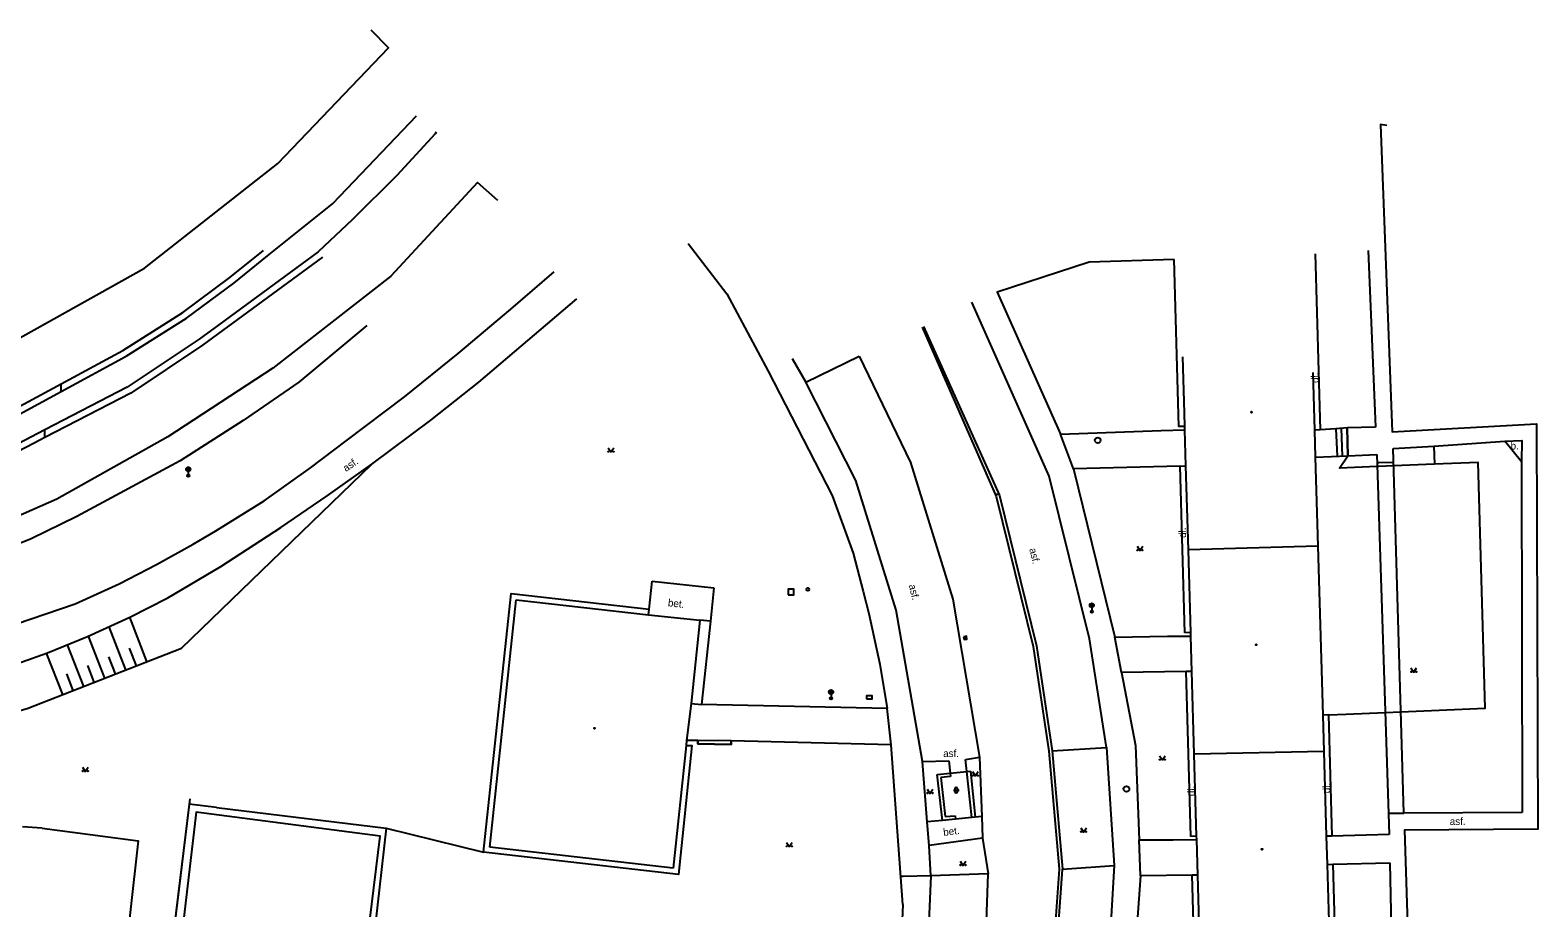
# Model space of a CAD drawing. Extents: x -602419 to -601554, y -1162937 to -1162362.
# Drawn here: x -601838.6 to -601705.2, y -1162455.9 to -1162378.3 of the extents above; entities that cross this region are included whole.
import ezdxf

# ---------------------------------------------------------------- set-up
doc = ezdxf.new("R2010")
doc.units = 0
doc.layers.add('Podklad', color=7, linetype='Continuous')

msp = doc.modelspace()

# ---------------------------------------------------------------- linework, layer by layer
at = {"layer": 'Podklad'}
for p, q in [((-601824.7525, -1162417.25), (-601824.4875, -1162416.985)), ((-601824.7525, -1162416.985), (-601824.4875, -1162417.25)), ((-601824.62, -1162417.305), (-601824.62, -1162417.68)), ((-601744.8325, -1162429.28), (-601744.5675, -1162429.015)), ((-601744.8325, -1162429.015), (-601744.5675, -1162429.28)), ((-601744.7, -1162429.335), (-601744.7, -1162429.71)), ((-601755.9198, -1162431.9066), (-601755.8802, -1162432.1534)), ((-601767.8925, -1162436.95), (-601767.6275, -1162436.685)), ((-601767.8925, -1162436.685), (-601767.6275, -1162436.95)), ((-601767.76, -1162437.005), (-601767.76, -1162437.38)), ((-601756.943, -1162445.488), (-601756.443, -1162445.488)), ((-601756.818, -1162445.363), (-601756.818, -1162445.613)), ((-601756.568, -1162445.363), (-601756.568, -1162445.613))]:
    msp.add_line(p, q, dxfattribs=at)
for points in [[(-601865.9699, -1162413.44), (-601868.073, -1162416.225), (-601860.681, -1162414.433), (-601851.512, -1162411.249), (-601843.288, -1162407.585), (-601828.487, -1162399.344), (-601816.71, -1162390.08), (-601806.918, -1162379.855), (-601808.45, -1162378.3)], [(-601898.07, -1162425.19), (-601894.4699, -1162425.26), (-601889.76, -1162425.42), (-601879.08, -1162424.2199), (-601865.29, -1162421.68), (-601852.18, -1162417.85), (-601841.55, -1162413.2199), (-601839.55, -1162412.24), (-601835.86, -1162410.24), (-601830.12, -1162407.13), (-601824.77, -1162403.76), (-601820.58, -1162400.6599), (-601817.6, -1162398.25), (-601811.85, -1162393.6599), (-601811.18, -1162392.96), (-601804.44, -1162385.87)], [(-601802.7, -1162387.31), (-601802.79, -1162387.45), (-601806.1599, -1162391.14), (-601810.09, -1162395.04), (-601813.14, -1162397.9), (-601821.9099, -1162404.34), (-601823.6599, -1162405.63), (-601830.02, -1162409.87), (-601837.31, -1162413.64), (-601838.54, -1162414.28), (-601842.26, -1162416.2199), (-601851.73, -1162420.1), (-601864.69, -1162423.83), (-601878.79, -1162426.46), (-601889.23, -1162427.52), (-601894.11, -1162427.5), (-601898.33, -1162427.48)], [(-601718.62, -1162386.7199), (-601719.1599, -1162386.65), (-601718.15, -1162413.82), (-601705.36, -1162413.11), (-601705.25, -1162448.94), (-601717.05, -1162449.02), (-601716.04, -1162480.32), (-601716.4099, -1162484.2199), (-601717.94, -1162489.4099), (-601746.45, -1162544.74), (-601749.56, -1162549.13)], [(-601797.24, -1162393.36), (-601799.042, -1162391.753), (-601806.692, -1162400.048), (-601817.129, -1162408.181), (-601826.438, -1162414.264), (-601836.254, -1162419.771), (-601849.065, -1162425.393), (-601857.06, -1162427.881), (-601870.816, -1162431.084), (-601881.829, -1162432.559), (-601893.35, -1162433.204), (-601893.374, -1162435.473)], [(-601898, -1162424.6), (-601894.45, -1162424.6599), (-601889.78, -1162424.82), (-601879.17, -1162423.62), (-601865.43, -1162421.1), (-601852.38, -1162417.28), (-601841.8, -1162412.68), (-601839.83, -1162411.71), (-601835.86, -1162409.56), (-601830.42, -1162406.61), (-601825.11, -1162403.27), (-601820.95, -1162400.18), (-601817.9699, -1162397.78)], [(-601780.39, -1162397.1599), (-601776.99, -1162401.62), (-601773.33, -1162408.45), (-601767.68, -1162419.45)], [(-601724.96, -1162398.06), (-601724.5, -1162413.64)], [(-601720.26, -1162397.79), (-601719.62, -1162413.39)], [(-601812.75, -1162398.36), (-601823.35, -1162406.15), (-601829.71, -1162410.39), (-601837.31, -1162414.32), (-601838.26, -1162414.81), (-601842.01, -1162416.77), (-601851.54, -1162420.6599), (-601864.55, -1162424.4099), (-601878.7, -1162427.06), (-601889.2, -1162428.12), (-601894.11, -1162428.1), (-601898.4, -1162428.09)], [(-601737.4099, -1162398.58), (-601744.95, -1162398.8), (-601753.06, -1162401.4699), (-601747.4699, -1162414.01), (-601738.57, -1162413.69), (-601736.4699, -1162413.64)], [(-601736.48, -1162413.34), (-601736.99, -1162413.35), (-601737.4099, -1162398.58)], [(-601834.62, -1162429.02), (-601830.7199, -1162427.24), (-601827.43, -1162425.54), (-601824.2, -1162423.73), (-601822.17, -1162422.57), (-601817.9099, -1162419.9), (-601813.81, -1162416.99), (-601810.64, -1162414.6), (-601805.48, -1162410.71), (-601800.75, -1162406.88), (-601796.1, -1162402.96), (-601792.25, -1162399.6599)], [(-601798.92, -1162409.4099), (-601790.24, -1162402.04)], [(-601743.4, -1162441.71), (-601744.9099, -1162432.12), (-601748.4699, -1162417.7199), (-601755.3, -1162402.35)], [(-601808.82, -1162404.4), (-601814.83, -1162409.42), (-601819.76, -1162412.82), (-601825.35, -1162416.38), (-601834.49, -1162421.29), (-601838.52, -1162423.27), (-601845.5, -1162426.1)], [(-601759.7, -1162404.55), (-601753.15, -1162419.52), (-601749.88, -1162432.78), (-601748.51, -1162442.04), (-601747.59, -1162452.46), (-601748.62, -1162466.9), (-601751, -1162479.06), (-601751.81, -1162481.88), (-601753.73, -1162488.54)], [(-601759.6, -1162404.5), (-601752.86, -1162419.44), (-601749.59, -1162432.7199), (-601748.21, -1162442.01)], [(-601771.2, -1162407.34), (-601770, -1162409.43)], [(-601770, -1162409.43), (-601765.28, -1162407.12)], [(-601765.28, -1162407.12), (-601760.74, -1162416.52), (-601756.98, -1162428.6), (-601754.64, -1162442.58)], [(-601736.51, -1162412.13), (-601736.65, -1162407.19)], [(-601725.15, -1162408.56), (-601725, -1162413.6599)], [(-601835.86, -1162410.24), (-601835.86, -1162409.56)], [(-601808.38, -1162416.6599), (-601803.17, -1162412.77), (-601798.92, -1162409.4099)], [(-601765.57, -1162418.11), (-601770, -1162409.43)], [(-601736.48, -1162413.34), (-601736.51, -1162412.13)], [(-601837.31, -1162414.32), (-601837.31, -1162413.64)], [(-601746.32, -1162417.07), (-601747.4699, -1162414.01)], [(-601736.4699, -1162413.64), (-601736.48, -1162413.34)], [(-601736.38, -1162416.81), (-601736.4699, -1162413.64)], [(-601724.5, -1162413.64), (-601725, -1162413.6599)], [(-601725, -1162413.6599), (-601724.94, -1162416.06)], [(-601723.12, -1162413.55), (-601724.5, -1162413.64)], [(-601722.12, -1162413.45), (-601723.12, -1162413.55)], [(-601723.12, -1162413.55), (-601723.01, -1162415.9699)], [(-601714.38, -1162416.67), (-601718.004, -1162416.8242), (-601719.31, -1162416.8799), (-601719.4651, -1162416.8868), (-601722.79, -1162417.0299), (-601722.06, -1162415.93), (-601722.12, -1162413.45)], [(-601722.53, -1162415.95), (-601722.62, -1162413.5)], [(-601719.62, -1162413.39), (-601722.12, -1162413.45)], [(-601722.12, -1162413.45), (-601722.06, -1162415.93)], [(-601787.48, -1162415.215), (-601787.23, -1162415.59), (-601786.98, -1162415.215)], [(-601718.05, -1162415.28), (-601714.44, -1162415.07)], [(-601717.09, -1162447.52), (-601718.05, -1162415.28)], [(-601714.44, -1162415.07), (-601708.1599, -1162414.63)], [(-601714.44, -1162415.07), (-601714.38, -1162416.67)], [(-601708.1599, -1162414.63), (-601706.68, -1162414.58), (-601706.7, -1162416.45)], [(-601706.7, -1162416.45), (-601708.1599, -1162414.63)], [(-601893.37, -1162444.62), (-601884.84, -1162446.24), (-601877.27, -1162446.73), (-601857.63, -1162443.6), (-601838.87, -1162438.26), (-601825.21, -1162432.93), (-601808.38, -1162416.6599)], [(-601848.2199, -1162436.84), (-601842, -1162435.09), (-601837.07, -1162433.34), (-601833.53, -1162431.9), (-601829.8, -1162430.19), (-601826.44, -1162428.48), (-601821.73, -1162425.7), (-601816.42, -1162422.27), (-601812.33, -1162419.46), (-601808.38, -1162416.6599)], [(-601736.88, -1162416.83), (-601746.32, -1162417.07), (-601742.68, -1162431.95), (-601738.02, -1162431.87), (-601735.94, -1162431.86)], [(-601736.88, -1162416.83), (-601736.38, -1162416.81)], [(-601736.46, -1162431.57), (-601736.88, -1162416.83)], [(-601736.1599, -1162424.24), (-601736.38, -1162416.81)], [(-601724.94, -1162416.06), (-601722.06, -1162415.93)], [(-601724.94, -1162416.06), (-601724.7, -1162423.9099)], [(-601723.78, -1162438.84), (-601722.2, -1162438.76), (-601718.7599, -1162438.6171), (-601717.3568, -1162438.5588), (-601709.92, -1162438.2499), (-601710.52, -1162416.51), (-601714.38, -1162416.67)], [(-601722.06, -1162415.93), (-601719.5, -1162415.81)], [(-601719.5, -1162415.81), (-601718.4099, -1162449.4)], [(-601718.013, -1162416.5223), (-601719.32, -1162416.5599), (-601719.4755, -1162416.5644)], [(-601706.7, -1162416.45), (-601706.65, -1162447.45)], [(-601762.02, -1162429.58), (-601765.57, -1162418.11)], [(-601767.68, -1162419.45), (-601765.82, -1162424.53), (-601764.93, -1162427.92), (-601764.42, -1162429.87), (-601763.45, -1162434.35), (-601762.8, -1162438.26)], [(-601752.9016, -1162419.3479), (-601753.225, -1162419.348)], [(-601740.7, -1162423.925), (-601740.45, -1162424.3), (-601740.2, -1162423.925)], [(-601724.7, -1162423.9099), (-601736.1599, -1162424.24)], [(-601735.95, -1162431.56), (-601736.1599, -1162424.24)], [(-601724.7, -1162423.9099), (-601724.28, -1162438.85)], [(-601783.86, -1162429.48), (-601783.59, -1162427.01)], [(-601783.59, -1162427.01), (-601778.13, -1162427.61)], [(-601780.58, -1162441.54), (-601780.09, -1162441.54), (-601781.27, -1162452.93), (-601798.5, -1162450.98), (-601796.06, -1162428.1), (-601783.86, -1162429.48)], [(-601797.95, -1162450.54), (-601795.62, -1162428.6599)], [(-601795.62, -1162428.6599), (-601783.92, -1162429.98)], [(-601778.13, -1162427.61), (-601778.44, -1162430.56)], [(-601848.83, -1162433.85), (-601834.62, -1162429.02)], [(-601828.27, -1162434.12), (-601829.8, -1162430.19)], [(-601783.92, -1162429.98), (-601783.86, -1162429.48)], [(-601783.92, -1162429.98), (-601779.36, -1162430.4699)], [(-601759.69, -1162442.94), (-601762.02, -1162429.58)], [(-601830.13, -1162434.85), (-601831.62, -1162431.05)], [(-601779.36, -1162430.4699), (-601780.15, -1162437.84)], [(-601778.44, -1162430.56), (-601779.36, -1162430.4699)], [(-601778.44, -1162430.56), (-601779.2199, -1162437.9)], [(-601833.86, -1162436.31), (-601835.29, -1162432.64)], [(-601832, -1162435.58), (-601833.45, -1162431.86)], [(-601742.08, -1162435.09), (-601742.68, -1162431.95)], [(-601735.95, -1162431.56), (-601736.46, -1162431.57)], [(-601735.94, -1162431.86), (-601735.95, -1162431.56)], [(-601735.86, -1162434.99), (-601735.94, -1162431.86)], [(-601835.7199, -1162437.03), (-601837.15, -1162433.37)], [(-601831.07, -1162435.21), (-601831.65, -1162433.71)], [(-601829.2, -1162434.49), (-601829.81, -1162432.94)], [(-601834.79, -1162436.67), (-601835.36, -1162435.21)], [(-601832.93, -1162435.94), (-601833.5, -1162434.4699)], [(-601736.36, -1162435), (-601742.08, -1162435.09), (-601740.85, -1162441.53), (-601740.51, -1162449.88), (-601737.52, -1162449.89), (-601735.42, -1162449.86)], [(-601735.86, -1162434.99), (-601736.36, -1162435)], [(-601735.94, -1162449.58), (-601736.36, -1162435)], [(-601735.64, -1162442.31), (-601735.86, -1162434.99)], [(-601716.4699, -1162434.675), (-601716.2199, -1162435.05), (-601715.9699, -1162434.675)], [(-601780.15, -1162437.84), (-601780.54, -1162441.09)], [(-601780.15, -1162437.84), (-601779.2199, -1162437.9)], [(-601762.8, -1162438.26), (-601779.2199, -1162437.9)], [(-601762.44, -1162441.48), (-601762.8, -1162438.26)], [(-601723.78, -1162438.84), (-601724.28, -1162438.85)], [(-601724.28, -1162438.85), (-601724.18, -1162442.08)], [(-601723.78, -1162438.84), (-601723.4699, -1162449.54)], [(-601780.58, -1162441.54), (-601781.7199, -1162452.37)], [(-601780.54, -1162441.09), (-601780.58, -1162441.54)], [(-601762.44, -1162441.48), (-601776.6, -1162441.14), (-601779.54, -1162441.1), (-601780.54, -1162441.09)], [(-601779.54, -1162441.1), (-601779.54, -1162441.3999), (-601776.6, -1162441.4399), (-601776.6, -1162441.14)], [(-601776.6, -1162441.14), (-601776.6, -1162441.44), (-601779.54, -1162441.4), (-601779.54, -1162441.1)], [(-601761.4099, -1162455.6), (-601762.44, -1162441.48)], [(-601748.21, -1162442.01), (-601743.4, -1162441.71)], [(-601748.21, -1162442.01), (-601747.29, -1162452.46)], [(-601743.4, -1162441.71), (-601742.71, -1162452.15)], [(-601724.18, -1162442.08), (-601735.64, -1162442.31)], [(-601724.18, -1162442.08), (-601723.9699, -1162449.56)], [(-601833.98, -1162443.455), (-601833.73, -1162443.83), (-601833.48, -1162443.455)], [(-601759.69, -1162442.94), (-601757.34, -1162442.9)], [(-601759.26, -1162448.3), (-601759.69, -1162442.94)], [(-601757.34, -1162442.9), (-601757.24, -1162443.99)], [(-601755.86, -1162442.78), (-601754.64, -1162442.58)], [(-601755.75, -1162443.85), (-601755.86, -1162442.78)], [(-601754.64, -1162442.58), (-601754.44, -1162447.81)], [(-601738.71, -1162442.445), (-601738.46, -1162442.82), (-601738.21, -1162442.445)], [(-601735.43, -1162449.56), (-601735.64, -1162442.31)], [(-601758.39, -1162444.1), (-601757.24, -1162443.99)], [(-601757.92, -1162448.1599), (-601758.39, -1162444.1)], [(-601757.21, -1162444.29), (-601758.06, -1162444.37)], [(-601758.06, -1162444.37), (-601757.6599, -1162447.83)], [(-601757.24, -1162443.99), (-601755.75, -1162443.85)], [(-601757.24, -1162443.99), (-601757.21, -1162444.29)], [(-601755.75, -1162443.85), (-601755.44, -1162443.82)], [(-601755.31, -1162447.9), (-601755.75, -1162443.85)], [(-601755.44, -1162443.82), (-601755.01, -1162447.87)], [(-601755.26, -1162443.8449), (-601755.01, -1162444.2199), (-601754.76, -1162443.8449)], [(-601759.27, -1162445.395), (-601759.02, -1162445.77), (-601758.77, -1162445.395)], [(-601769.18, -1162491.29), (-601808.78, -1162486.76), (-601826.77, -1162484.63), (-601826.06, -1162478.28), (-601826.06, -1162478.24), (-601826, -1162477.71), (-601813.39, -1162479.15), (-601811.31, -1162479.39), (-601807.65, -1162449.55), (-601823.91, -1162447.44), (-601827.44, -1162477.36), (-601827.52, -1162478.12), (-601828.2, -1162484.27), (-601829.06, -1162484.16), (-601831.79, -1162483.87), (-601832.64, -1162483.78)], [(-601822.13, -1162447.02), (-601824.55, -1162446.72), (-601828.37, -1162478.04), (-601827.52, -1162478.12), (-601826.06, -1162478.28)], [(-601824.49, -1162446.24), (-601828.24, -1162476.98)], [(-601822.13, -1162447.02), (-601807.12, -1162448.84), (-601810.61, -1162479.89), (-601826.06, -1162478.28)], [(-601718.4706, -1162447.5306), (-601717.09, -1162447.52)], [(-601706.65, -1162447.45), (-601717.09, -1162447.52)], [(-601837.55, -1162448.85), (-601839.27, -1162448.74)], [(-601837.55, -1162448.85), (-601829.04, -1162449.96), (-601832.49, -1162480.85)], [(-601807.12, -1162448.8399), (-601798.5, -1162450.98)], [(-601757.92, -1162448.1599), (-601759.26, -1162448.3)], [(-601759.09, -1162450.37), (-601759.26, -1162448.3)], [(-601756.76, -1162448.04), (-601757.92, -1162448.1599)], [(-601757.6599, -1162447.83), (-601756.79, -1162447.75)], [(-601756.79, -1162447.75), (-601756.76, -1162448.04)], [(-601755.31, -1162447.9), (-601756.76, -1162448.04)], [(-601755.01, -1162447.87), (-601755.31, -1162447.9)], [(-601754.44, -1162447.81), (-601755.01, -1162447.87)], [(-601754.44, -1162447.81), (-601754.37, -1162449.74)], [(-601745.68, -1162448.815), (-601745.43, -1162449.19), (-601745.18, -1162448.815)], [(-601771.71, -1162450.105), (-601771.46, -1162450.48), (-601771.21, -1162450.105)], [(-601754.37, -1162449.74), (-601759.09, -1162450.37)], [(-601754.37, -1162449.74), (-601753.88, -1162452.88)], [(-601740.4, -1162453.07), (-601740.51, -1162449.88)], [(-601735.43, -1162449.56), (-601735.94, -1162449.58)], [(-601735.42, -1162449.86), (-601735.43, -1162449.56)], [(-601735.33, -1162452.99), (-601735.42, -1162449.86)], [(-601723.4699, -1162449.54), (-601723.9699, -1162449.56)], [(-601723.9699, -1162449.56), (-601723.89, -1162452.06)], [(-601718.4099, -1162449.4), (-601723.4699, -1162449.54)], [(-601781.7199, -1162452.37), (-601797.95, -1162450.54)], [(-601758.94, -1162453.05), (-601759.09, -1162450.37)], [(-601756.35, -1162451.765), (-601756.1, -1162452.14), (-601755.85, -1162451.765)], [(-601750.71, -1162479.13), (-601748.32, -1162466.94), (-601747.29, -1162452.46)], [(-601747.29, -1162452.46), (-601742.71, -1162452.15)], [(-601742.71, -1162452.15), (-601743.65, -1162467.7)], [(-601723.89, -1162452.06), (-601723.39, -1162452.04)], [(-601723.89, -1162452.06), (-601723.6599, -1162460.06)], [(-601723.39, -1162452.04), (-601718.35, -1162451.9)], [(-601723.39, -1162452.04), (-601722.94, -1162467.8)], [(-601718.35, -1162451.9), (-601718.01, -1162467.6599)], [(-601758.94, -1162453.05), (-601759.31, -1162461.84), (-601760.52, -1162469.84), (-601761.77, -1162476.23)], [(-601758.94, -1162453.05), (-601761.39, -1162453.1199), (-601761.5904, -1162453.1256)], [(-601753.88, -1162452.88), (-601758.94, -1162453.05)], [(-601756.88, -1162477.28), (-601755.39, -1162470.09), (-601754.18, -1162462.14), (-601753.88, -1162452.88)], [(-601735.84, -1162453.01), (-601740.4, -1162453.07), (-601741.48, -1162468.11), (-601736.96, -1162467.96), (-601734.9, -1162467.85)], [(-601735.33, -1162452.99), (-601735.84, -1162453.01)], [(-601735.4099, -1162467.56), (-601735.84, -1162453.01)], [(-601735.12, -1162460.39), (-601735.33, -1162452.99)], [(-601761.4099, -1162455.6), (-601761.64, -1162461.06), (-601762.9699, -1162469.44)]]:
    msp.add_lwpolyline(points, dxfattribs=at)
for points in [[(-601771.56, -1162428.23), (-601771.06, -1162428.23), (-601771.06, -1162427.73), (-601771.56, -1162427.73)], [(-601756.0432, -1162431.9264), (-601756.0036, -1162432.1732), (-601755.7568, -1162432.1336), (-601755.7964, -1162431.8868)], [(-601764.64, -1162437.405), (-601764.14, -1162437.405), (-601764.14, -1162437.155), (-601764.64, -1162437.155)]]:
    msp.add_lwpolyline(points, close=True, dxfattribs=at)
for centre, radius in [((-601730.58, -1162412.07), 0.045), ((-601730.58, -1162412.07), 0.0199), ((-601744.18, -1162414.56), 0.25), ((-601787.4551, -1162415.5649), 0.025), ((-601787.0054, -1162415.5649), 0.025), ((-601824.62, -1162417.1175), 0.1875), ((-601824.62, -1162417.68), 0.1), ((-601824.62, -1162417.68), 0.0723), ((-601824.62, -1162417.68), 0.0438), ((-601740.6751, -1162424.2749), 0.025), ((-601740.2254, -1162424.2749), 0.025), ((-601769.82, -1162427.74), 0.125), ((-601744.7, -1162429.1475), 0.1875), ((-601744.7, -1162429.71), 0.1), ((-601744.7, -1162429.71), 0.0723), ((-601744.7, -1162429.71), 0.0438), ((-601730.17, -1162432.63), 0.045), ((-601730.17, -1162432.63), 0.0199), ((-601716.445, -1162435.0249), 0.025), ((-601715.9953, -1162435.0249), 0.025), ((-601767.76, -1162436.8175), 0.1875), ((-601767.76, -1162437.38), 0.1), ((-601767.76, -1162437.38), 0.0723), ((-601767.76, -1162437.38), 0.0438), ((-601788.68, -1162440.01), 0.045), ((-601788.68, -1162440.01), 0.0199), ((-601738.6851, -1162442.7949), 0.025), ((-601738.2354, -1162442.7949), 0.025), ((-601833.9551, -1162443.8049), 0.025), ((-601833.5054, -1162443.8049), 0.025), ((-601755.2351, -1162444.1948), 0.025), ((-601754.7854, -1162444.1948), 0.025), ((-601759.2451, -1162445.7449), 0.025), ((-601758.7954, -1162445.7449), 0.025), ((-601741.64, -1162445.38), 0.25), ((-601745.6551, -1162449.1649), 0.025), ((-601745.2054, -1162449.1649), 0.025), ((-601771.6851, -1162450.4549), 0.025), ((-601771.2354, -1162450.4549), 0.025), ((-601729.65, -1162450.71), 0.045), ((-601729.65, -1162450.71), 0.0199), ((-601756.3251, -1162452.1149), 0.025), ((-601755.8754, -1162452.1149), 0.025)]:
    msp.add_circle(centre, radius, dxfattribs=at)
for centre, start, end in [((-601756.6929, -1162445.3631), 0, 180), ((-601756.6929, -1162445.6131), 180, 0)]:
    msp.add_arc(centre, 0.125, start, end, dxfattribs=at)

# ---------------------------------------------------------------- texts
for s, rotation, p in [('dl.', 91.65, (-601724.64, -1162409.48)), ('asf.', 34.72, (-601810.67, -1162417.37)), ('dl.', 91.65, (-601736.36, -1162423.18)), ('asf.', 283.83, (-601750.24, -1162424.18)), ('asf.', 283.83, (-601760.9, -1162427.37)), ('bet.', 353.45, (-601782.2199, -1162429.2199)), ('dl.', 91.65, (-601735.59, -1162446.01)), ('dl.', 91.65, (-601723.61, -1162445.75)), ('bet.', 7.6, (-601757.8, -1162449.54)), ('asf.', 0.39, (-601713.04, -1162448.57))]:
    msp.add_text(s, height=0.65, rotation=rotation, dxfattribs=at).set_placement(p)
for s, p in [('b.', (-601707.6599, -1162415.37)), ('asf.', (-601757.85, -1162442.56))]:
    msp.add_text(s, height=0.65, dxfattribs=at).set_placement(p)

doc.saveas('drawing.dxf')
